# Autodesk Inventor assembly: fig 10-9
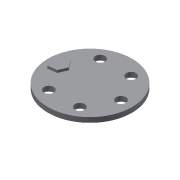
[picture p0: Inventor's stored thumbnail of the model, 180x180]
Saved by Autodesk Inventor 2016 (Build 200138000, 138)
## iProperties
Created: 2008-05
Part Number: fig 10-9
Document SubType Name: Assembly
Designer: CADCIM
Author: CADCIM
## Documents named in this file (3)
- D:\KAVITA\Autodesk Inventor_ 2016 Project_Kavita\Inventor_Part Files\Inventor_2016_Part\c10_Inv_2016\c10_inv_2016_prt\fig 10-9.iam
- D:\KAVITA\Autodesk Inventor_ 2016 Project_Kavita\Inventor_Part Files\Inventor_2016_Part\c10_Inv_2016\c10_inv_2016_prt\Part4.ipt
- D:\KAVITA\Autodesk Inventor_ 2016 Project_Kavita\Inventor_Part Files\Inventor_2016_Part\c10_Inv_2016\c10_inv_2016_prt\Part5.ipt
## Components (2 placed, 2 different names)
1. Part4:1
2. Part5:1
